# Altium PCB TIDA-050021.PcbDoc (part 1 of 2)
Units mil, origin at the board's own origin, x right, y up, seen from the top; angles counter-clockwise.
Board outline 3800 x 2400 mil, 4 copper layers (Top Layer, Signal Layer 1, Signal Layer 2, Bottom Layer), stack 51.2 mil thick; 78 components, 31 nets, 172 pads, 126 vias.
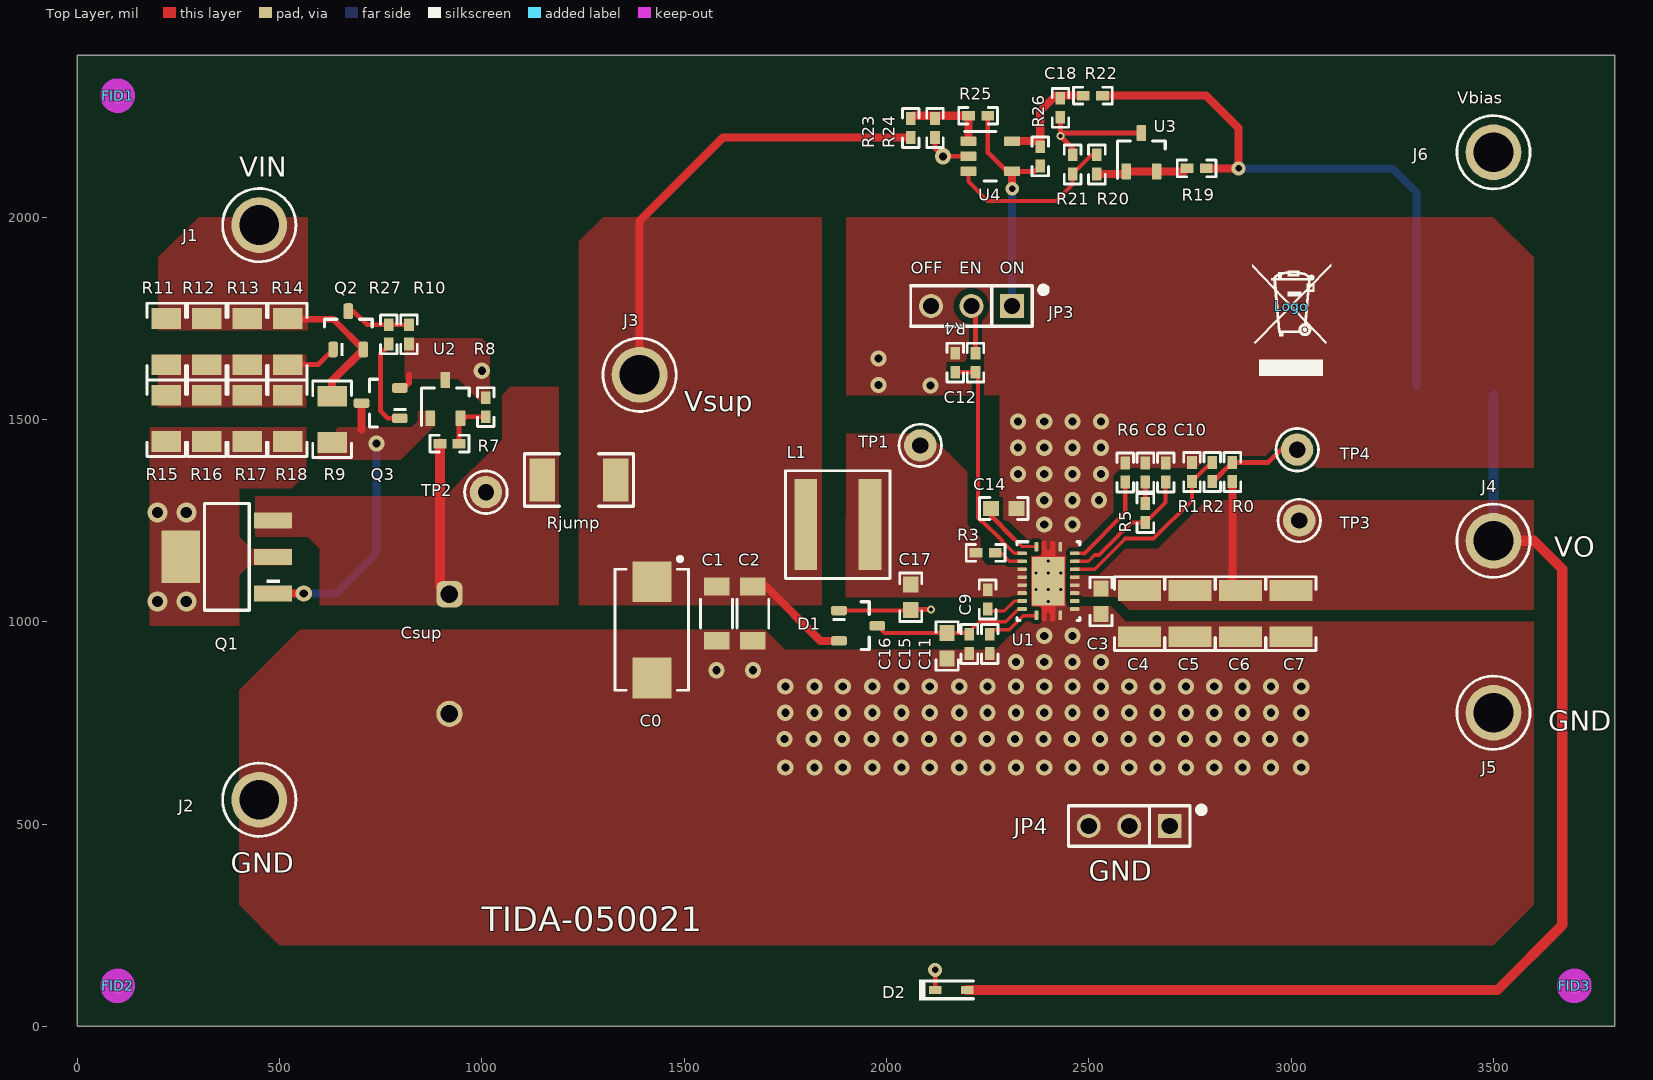
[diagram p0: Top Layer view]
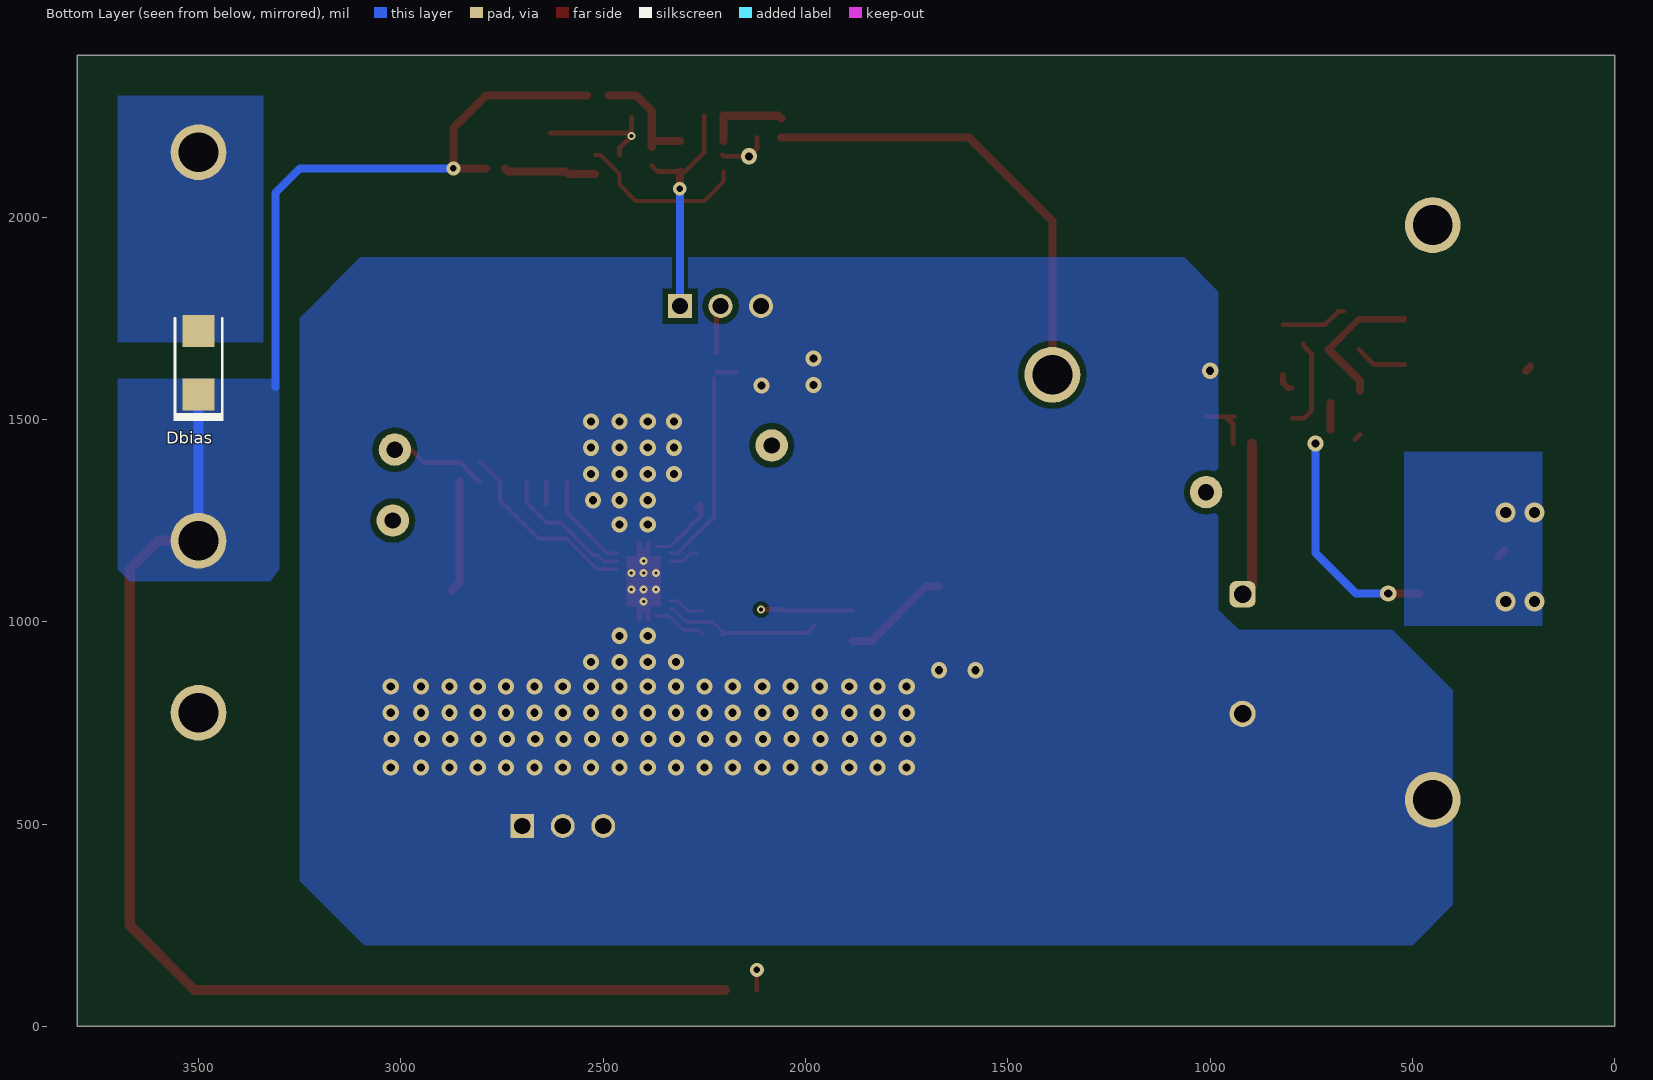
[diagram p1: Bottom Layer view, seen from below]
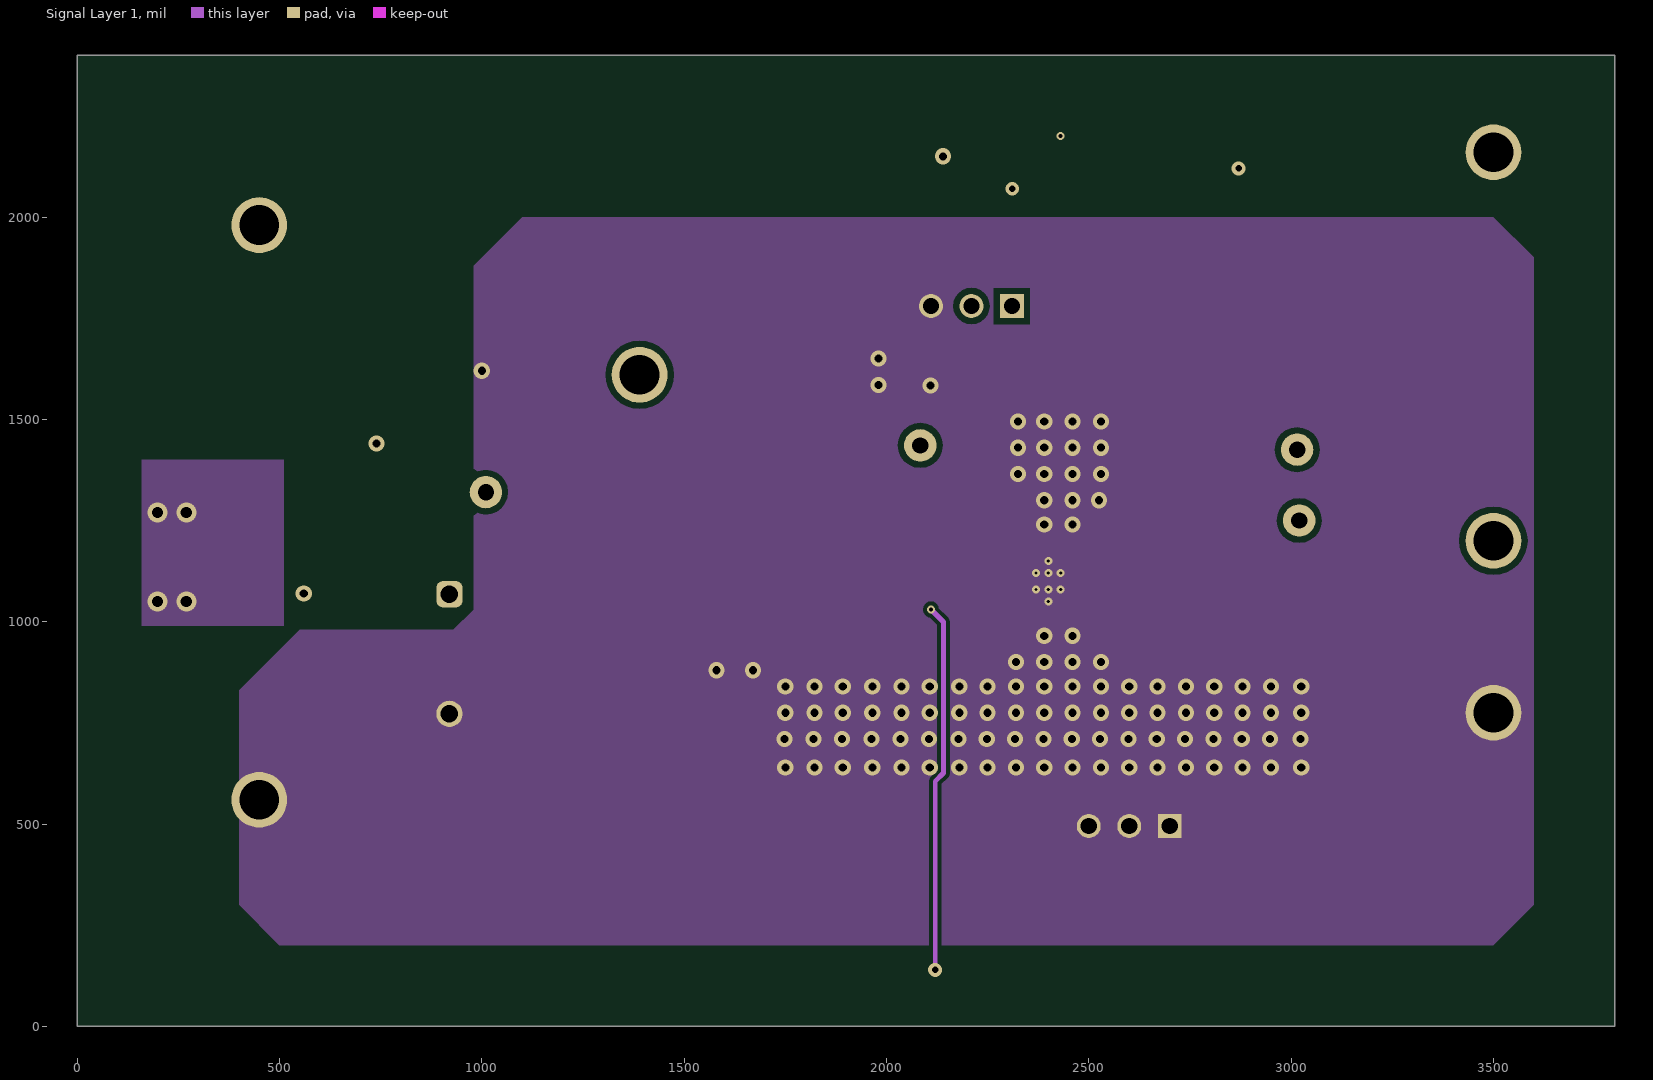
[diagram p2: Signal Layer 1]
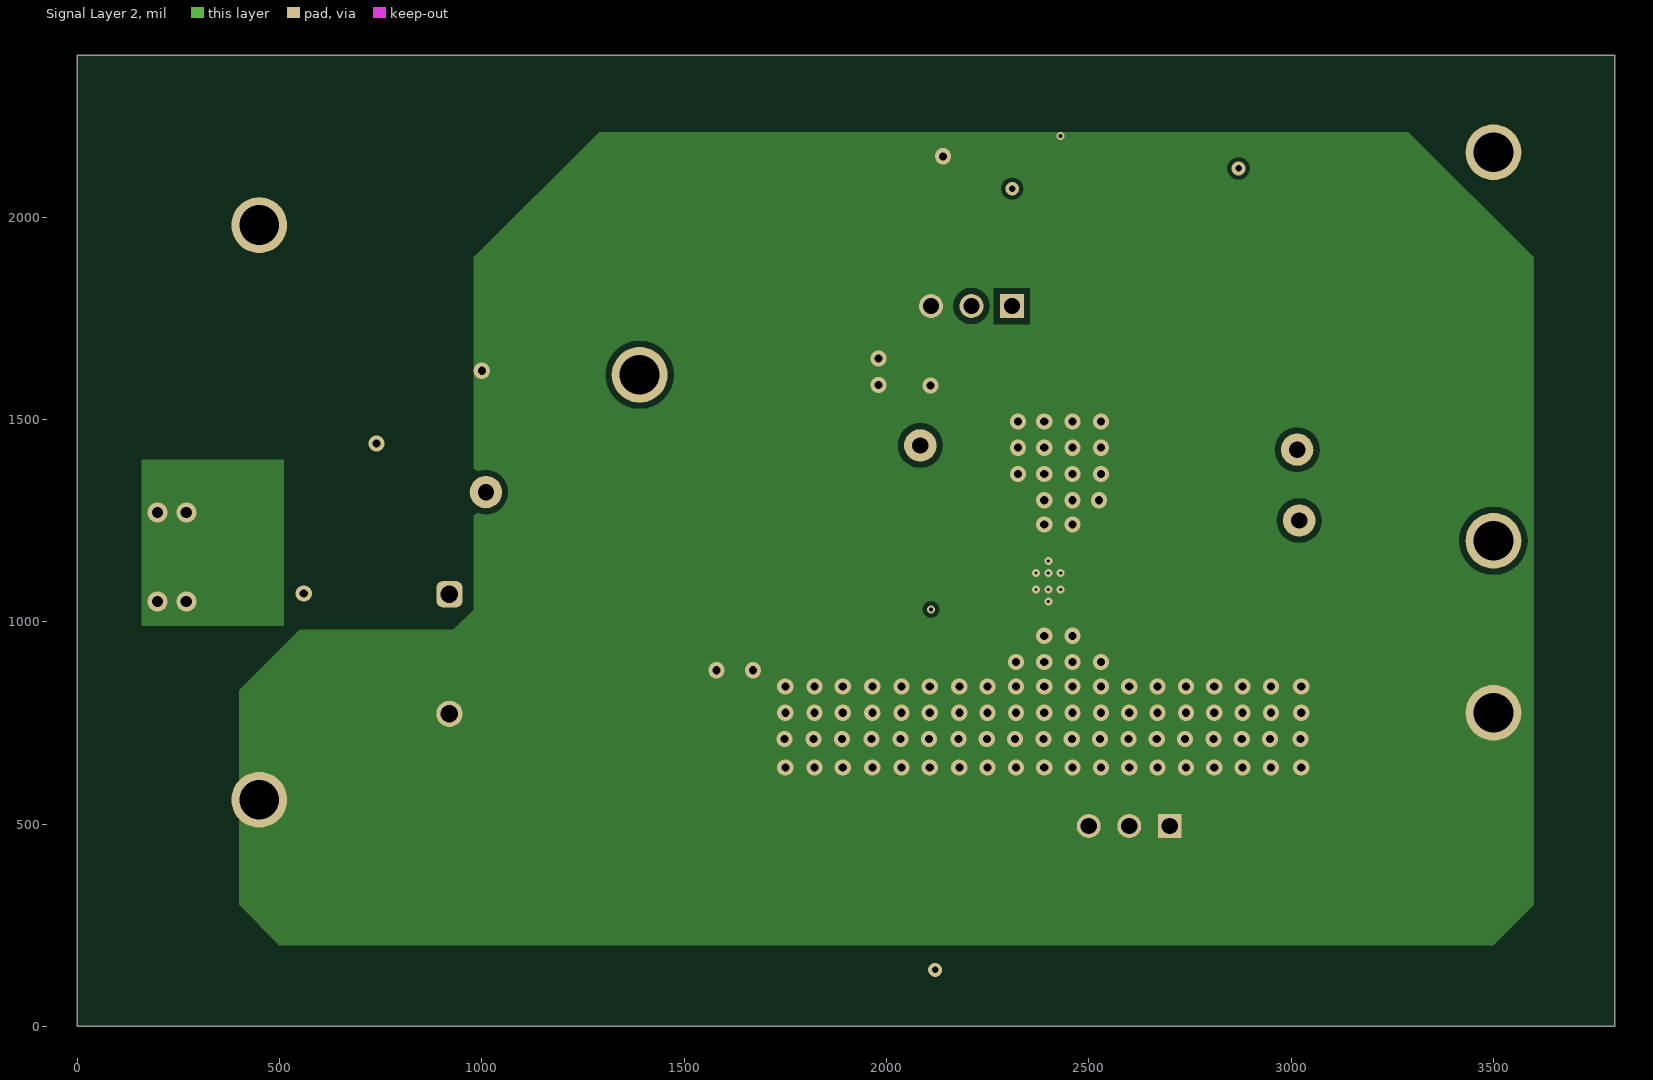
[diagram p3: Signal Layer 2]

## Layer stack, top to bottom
Top Solder: solder mask 0.4, Solder Resist, Dk 3.5
Top Layer: signal copper 2.8
Dielectric1: core 10, FR-4, Dk 4.8
Signal Layer 1: signal copper 2.8
Dielectric 3: dielectric 20, Dk 4.2
Signal Layer 2: signal copper 2.8
Dielectric 2: dielectric 10, Dk 4.8
Bottom Layer: signal copper 2.8
Bottom Solder: solder mask 0.4, Solder Resist, Dk 3.5

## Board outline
0,0 3800,0 3800,2400 0,2400

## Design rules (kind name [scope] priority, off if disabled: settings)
AcuteAngle [All] p1: minimum=4.50000000000000E+0001 checktracksonly=FALSE
AssemblyTestPointUsage [All] p1: valid=2
BoardOutlineClearance BoardOutlineClearance_MountingHoles [OnCopper and InComponentClass('Mounting Holes')] p1: gap=40 ignorepadtopadclearanceinfootprint=FALSE
BoardOutlineClearance BoardOutlineClearance_Poly [OnCopper and IsPoly] p2: gap=25 ignorepadtopadclearanceinfootprint=FALSE
BoardOutlineClearance [OnCopper and Not InComponentClass('Logo') and not InComponentClass('FiducialMark') and not InRegion(1000,500,4000,800) and not InPoly] p3: gap=75 ignorepadtopadclearanceinfootprint=FALSE
Clearance Clearance_Keepouts [((IsTrack Or IsArc) And Not InPoly) And IsFree and IsKeepOut vs ((IsTrack Or IsArc) And Not InPoly) And IsFree and IsKeepOut] p1: gap=0 ignorepadtopadclearanceinfootprint=FALSE
Clearance Clearance_Poly [InPolygon] p2: gap=10 ignorepadtopadclearanceinfootprint=FALSE except(0: Arc-Hole Track-Hole SMDPad-Hole THPad-Hole Via-Hole Fill-Hole Poly-Hole Region-Hole Text-Hole; 12: Arc-Via Track-Via SMDPad-Via; 15: Arc-THPad Track-THPad SMDPad-THPad THPad-THPad THPad-Via THPad-Fill THPad-Poly THPad-Region)
Clearance Clearance_FiducialMark [IsKeepOut and InComponentClass('FiducialMark') vs IsPad and InComponentClass('FiducialMark')] p3: gap=0 ignorepadtopadclearanceinfootprint=FALSE
Clearance [All] p4: gap=7.87 ignorepadtopadclearanceinfootprint=FALSE except(0: Arc-Hole Track-Hole SMDPad-Hole THPad-Hole Via-Hole Fill-Hole Poly-Hole Region-Hole Text-Hole)
ComponentClearance ComponentClearance_MountingHoles_FiducialMarks [InComponentClass('Mounting Holes') vs InComponentClass('FiducialMark')] p1: gap=50 collisioncheckmode=3 verticalgap=10 showdistances=FALSE
ComponentClearance ComponentClearance_Shunt [InComponentClass('Header') vs InComponentClass('Shunt')] p2: gap=0 collisioncheckmode=3 verticalgap=0 showdistances=FALSE
ComponentClearance ComponentClearance_Logo [InComponentClass('Logo')] p3: gap=50 collisioncheckmode=3 verticalgap=10 showdistances=FALSE
ComponentClearance ComponentClearance_ScrewToNut [(HasFootprint('NY PMS 440 0025 PH')) vs (HasFootprint('Keystone_1902C'))] p4: gap=5 collisioncheckmode=3 verticalgap=10 showdistances=FALSE
ComponentClearance ComponentClearance_MountingHoles [InComponentClass('Mounting Holes')] p5: gap=250 collisioncheckmode=3 verticalgap=100000 showdistances=FALSE
ComponentClearance ComponentClearance_SmallPassives [HasFootprint('0201*') or HasFootprint('0402*') or HasFootprint('0508') or HasFootprint('0603*') or HasFootprint('0612') or HasFootprint('0805*') or HasFootprint('0815*') or HasFootprint('0830*') or HasFootprint('1206*') or HasFootprint('1210*') or HasFootprint('1808*') or HasFootprint('1812*') or HasFootprint('1825*') or HasFootprint('2010*') or HasFootprint('2220*') or HasFootprint('2225*') or HasFootprint('2512*') or HasFootprint('2728*') or HasFootprint('3518*') vs HasFootprint('0201*') or HasFootprint('0402*') or HasFootprint('0508') or HasFootprint('0603*') or HasFootprint('0612') or HasFootprint('0805*') or HasFootprint('0815*') or HasFootprint('0830*') or HasFootprint('1206*') or HasFootprint('1210*') or HasFootprint('1808*') or HasFootprint('1812*') or HasFootprint('1825*') or HasFootprint('2010*') or HasFootprint('2220*') or HasFootprint('2225*') or HasFootprint('2512*') or HasFootprint('2728*') or HasFootprint('3518*')] p6: gap=14.96 collisioncheckmode=3 verticalgap=10 showdistances=FALSE
ComponentClearance ComponentClearance_THtoSMT [IsThruComponent vs IsSMTComponent] p7: gap=40 collisioncheckmode=3 verticalgap=30 showdistances=FALSE
ComponentClearance ComponentClearance_THtoTH [IsThruComponent vs IsThruComponent] p8: gap=30 collisioncheckmode=3 verticalgap=30 showdistances=FALSE
ComponentClearance [All] p9: gap=30 collisioncheckmode=3 verticalgap=10 showdistances=FALSE
DiffPairsRouting [All] p1: maxlimit=100 minlimit=10 mostfreqgap=10 toplayer_minwidth=15 toplayer_maxwidth=15 toplayer_prefwidth=15 midlayer1_minwidth=15 midlayer1_maxwidth=15 midlayer1_prefwidth=15 midlayer2_minwidth=15 midlayer2_maxwidth=15 midlayer2_prefwidth=15 bottomlayer_minwidth=15 bottomlayer_maxwidth=15 bottomlayer_prefwidth=15 maxuncoupledlength=1000
FabricationTestPointUsage TestPointUsage [All] p1: valid=2 allowmultiple=FALSE
FabricationTestpoint Testpoint [All] p1: side=3 testpointundercomponent=TRUE minsize=40 maxsize=100 preferedsize=60 minholesize=0 maxholesize=40 preferedholesize=32 testpointgrid=1 allowsidetop=TRUE allowsidebottom=TRUE usegrid=TRUE gridtolerance=0.01
FanoutControl Fanout_LCC [IsLCC] p1: bgadir=Out bgaviamode=Centered fanoutstyle=Auto fanoutdirection=Alternating viagrid=1 // Fanout_LCC (Default Rule)
FanoutControl Fanout_BGA [IsBGA] p2: bgadir=Out bgaviamode=Centered fanoutstyle=Auto fanoutdirection=Alternating viagrid=1 // Fanout_BGA (Default Rule)
FanoutControl Fanout_Default [All] p4: bgadir=Out bgaviamode=Centered fanoutstyle=Auto fanoutdirection=Alternating viagrid=1 // Fanout_Default (Default Rule)
FanoutControl Fanout_Small [(CompPinCount < 5)] p5: bgadir=Out bgaviamode=Centered fanoutstyle=Auto fanoutdirection=OutThenIn viagrid=1 // Fanout_Small (Default Rule)
HoleSize [All] p1: absolutevalues=TRUE maxlimit=251 minlimit=7.87 maxpercent=80.000 minpercent=20.000
MinimumAnnularRing MinimumAnnularRing_ThermalPadVias [IsVia and InAnyComponent] p1: minimumring=5.91
MinimumAnnularRing [All] p2: minimumring=8
MinimumSolderMaskSliver MinimumSolderMaskSliver_Logo [InComponentClass('Logo') vs InComponentClass('Logo')] p1: minsoldermaskwidth=0.7
MinimumSolderMaskSliver [All] p2: minsoldermaskwidth=3.94
PlaneConnect [All] p1: planeconnectstyle=Relief reliefexpansion=10 reliefentries=4 reliefconductorwidth=10 reliefairgap=10
PolygonConnect [All] p1: connectstyle=Direct reliefconductorwidth=10 reliefentries=4 polygonreliefangle="90 Angle" airgapwidth=10
RoutingVias ThermalPadVias [IsVia and InAnyComponent] p1: holewidth=7.87 width=19.68 viastyle="Through Hole" minholewidth=7.87 minwidth=19.68 maxholewidth=12.99 maxwidth=23.62
RoutingVias [All] p2: holewidth=16 width=34 viastyle="Through Hole" minholewidth=7.87 minwidth=26 maxholewidth=40 maxwidth=65
SilkToBoardRegionClearance [Not ((IsComment or IsDesignator) And (Hide <> 'False')) and not InRegion(1000,500,4000,800)] p1:
SilkToSilkClearance SilkToSilkClearance_Pb-FreeLogo [(HasFootprint('Pb-Free_Overlay_Medium') OR HasFootprint('Pb-Free_Overlay_Small')) vs (HasFootprint('Pb-Free_Overlay_Medium') OR HasFootprint('Pb-Free_Overlay_Small'))] p1: silktosilkclearance=0
SilkToSilkClearance [All] p2: silktosilkclearance=4
SilkToSolderMaskClearance SilkToComponentPadClearance [(IsPad or IsFill or IsRegion) and InAnycomponent] p1: minsilkscreentomaskgap=5 clearancetoexposedcopper=TRUE
SilkToSolderMaskClearance "Silk to Solder Mask Opening" [All] p2: minsilkscreentomaskgap=4 clearancetoexposedcopper=FALSE
SolderMaskExpansion [All] p1: expansion=1.97
Width [All] p1: maxlimit=100 minlimit=6 preferedwidth=10 checkconnectedcopper=TRUE
15 further rules are at their usual default settings.

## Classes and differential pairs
component class Header: JP3 JP4
component class TIDA-050021: C0 C1 C2 C3 C4 C5 C6 C7 C8 C9 C10 C11 C12 C14 C15 C16 C17 C18 Csup D1 D2 Dbias J1 J2 J3 J4 J5 J6 JP3 JP4 L1 Q1 Q2 Q3 R0 R1 R2 R3 R4 R5 R6 R7 R8 R9 R10 R11 R12 R13 R14 R15 R16 R17 R18 R19 R20 R21 R22 R23 R24 R25 R26 R27 Rjump TP1 TP2 TP3 TP4 U1 U2 U3 U4
component class AssemblyNote: ZZ2 ZZ3 ZZ4
component class FiducialMark: FID1 FID2 FID3
component class TIDA-050021_Hardware: FID1 FID2 FID3 Logo ZZ2 ZZ3 ZZ4

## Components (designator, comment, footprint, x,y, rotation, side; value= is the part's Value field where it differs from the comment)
C0 "T495X107K016ATE100" 7343-43 1420,980 r270 top value=100uF
C1 "GRM31CR61C226KE15L" 1206_180 1580,1020 r270 top value=22uF
C2 "GRM31CR61C226KE15L" 1206_180 1670,1020 r270 top value=22uF
C3 "GRM188R71E105KA12D" 0603 2530,1050 r270 top value=1uF
C4 "GRM32ER71E226KE15L" 1210_270 2625,1020 r270 top value=22uF
C5 "GRM32ER71E226KE15L" 1210_270 2750,1020 r270 top value=22uF
C6 "GRM32ER71E226KE15L" 1210_270 2875,1020 r270 top value=22uF
C7 "GRM32ER71E226KE15L" 1210_270 3000,1020 r270 top value=22uF
C8 "CGA2B3X7R1H103K050BB" 0402 2640,1368.62 r90 top value=0.01uF
C9 "GRM155R61C104KA88D" 0402 2250,1055 r270 top value=0.1uF
C10 "GRM1555C1H470FA01D" 0402 2690,1368.62 r90 top value=47pF
C11 "GRM155R71C473KA01D" 0402 2255,945 r90 top value=0.047uF
C12 "GRM155R61H472KA01D" 0402 2170,1640 r90 top value=4700pF
C14 "0603ZD475KAT2A" 0603 2290,1280 r180 top value=4.7uF
C15 "GRM155R61C104KA88D" 0402 2205,945 r270 top value=0.1uF
C16 "GRM188R71E105KA12D" 0603 2150,940 r270 top value=1uF
C17 "GRM188R61E104KA01D" 0603 2060,1060 r270 top value=0.1uF
C18 "GRM155R61A104KA01D" 0402 2430,2270 r270 top value=0.1uF
Csup "HV1625-2R7256-R" HV_1600x2840 920,920 r270 top value=25000000uF
D1 "BAT54C-7-F" SOT-23 1930,990 r0 top value=30V
D2 "1N4148WT" Fairchild_SOD-523F 2160,90 r0 top value=75V
Dbias "MBRA210LT3G" SMA 3500,1640 r90 bottom value=10V
FID1 "Fiducial" Fiducial10-20 100,2300 r0 top
FID2 "Fiducial" Fiducial10-20 100,100 r0 top
FID3 "Fiducial" Fiducial10-20 3700,100 r0 top
J1 "Suggest using a net name here" Keystone1502-2 450,1980 r0 top value=Double
J2 "Suggest using a net name here" Keystone1502-2 450,560 r0 top value=Double
J3 "Suggest using a net name here" Keystone1502-2 1390,1610 r0 top value=Double
J4 "Suggest using a net name here" Keystone1502-2 3500,1200 r0 top value=Double
J5 "Suggest using a net name here" Keystone1502-2 3500,775 r0 top value=Double
J6 "Suggest using a net name here" Keystone1502-2 3500,2160 r0 top value=Double
JP3 "PEC03SAAN" CONN_PEC03SAAN 2210,1780 r180 top
JP4 "PEC03SAAN" CONN_PEC03SAAN 2600,495 r180 top
L1 "XAL6030-102MEB" XAL6030 1880,1240 r0 top value=1uH
Logo "WEEE logo" WEEE_Minimum 3000,1780 r0 top
Q1 "NSS40301MZ4T1G" SOT-223 370,1160 r180 top value="40 V"
Q2 "BC857C-7-F" SOT-23 670,1720 r90 top value="45 V"
Q3 "BC847CLT1G" SOT-23 750,1540 r180 top value="45 V"
R0 "CRCW040249R9FKED" 0402 2855,1370 r270 top value=49.9
R1 "CRCW040256K2FKED" 0402 2755,1370 r270 top value=56.2k
R2 "CRCW0402121KFKED" 0402 2805,1370 r270 top value=121k
R3 "CRCW0402255KFKED" 0402 2245,1170 r180 top value=255k
R4 "MCR01MZPF10R0" 0402 2220,1640 r270 top value=10.0
R5 "CRCW04024K99FKED" 0402 2640,1268.62 r270 top value=4.99k
R6 "CRCW040290K9FKED" 0402 2590,1368.62 r270 top value=90.9k
R7 "CRCW04026K04FKED" 0402 920,1440 r180 top value=6.04k
R8 "CRCW0402100KFKED" 0402 1010,1530 r270 top value=100k
R9 "CRCW120620R0FKEAHP" 1206 630,1500 r270 top value=20.0
R10 "ERJ-2RKF3300X" 0402 820,1710 r90 top value=330
R11 "CRCW12063R60JNEA" 1206 220,1692.36 r270 top value=3.6
R12 "CRCW12063R60JNEA" 1206 320,1692.36 r270 top value=3.6
R13 "CRCW12063R60JNEA" 1206 420,1692.36 r270 top value=3.6
R14 "CRCW12063R60JNEA" 1206 520,1692.36 r270 top value=3.6
R15 "CRCW12063R60JNEA" 1206 220,1502.36 r270 top value=3.6
R16 "CRCW12063R60JNEA" 1206 320,1502.36 r270 top value=3.6
R17 "CRCW12063R60JNEA" 1206 420,1502.36 r270 top value=3.6
R18 "CRCW12063R60JNEA" 1206 520,1502.36 r270 top value=3.6
R19 "CRCW04021K00FKED" 0402 2766.56,2120.2 r180 top value=1.00k
R20 "ERJ-2RKF1503X" 0402 2520,2130 r90 top value=150k
R21 "CRCW0402100KFKED" 0402 2460,2130 r270 top value=100k
R22 "MCR01MZPF10R0" 0402 2510,2300 r0 top value=10.0
R23 "CRCW0402100KFKED" 0402 2060,2220 r270 top value=100k
R24 "CRCW0402113KFKED" 0402 2120,2220 r90 top value=113k
R25 "CRCW0402316KFKED" 0402 2226.56,2250.2 r0 top value=316k
R26 "CRCW040210K0FKED" 0402 2380,2150 r90 top value=10.0k
R27 "CRCW0402100RFKED" 0402 770,1710 r270 top value=100
Rjump "CRCW20100000Z0EF" 2010 1240,1350 r180 top value=0
TP1 "5003" Keystone5003 2083.58,1435.64 r90 top value=Orange
TP2 "5003" Keystone5003 1010,1320 r90 top value=Orange
TP3 "5003" Keystone5003 3020,1250 r180 top value=Orange
TP4 "5003" Keystone5003 3015,1425 r0 top value=Orange
U1 "TPS61088QRHLTQ1" RHL0020A 2400,1100 r0 top
U2 "ATL431AIDBZR" DBZ0003A_N 910,1550 r90 top
U3 "ATL431AIDBZR" DBZ0003A_N 2630,2160 r90 top
U4 "LMV331IDBV" DBV0005A_N 2256.56,2150.2 r0 top
ZZ2 "These assemblies are ESD sensitive, ESD precautions shall be observed." AssemblyNote 185,3829.11 r0 top
ZZ3 "These assemblies must be clean and free from flux and all contaminants. Use of no clean flux is not acceptable." AssemblyNote 185,3740.56 r0 top
ZZ4 "These assemblies must comply with workmanship standards IPC-A-610 Class 2, unless otherwise specified." AssemblyNote 185,3652 r0 top

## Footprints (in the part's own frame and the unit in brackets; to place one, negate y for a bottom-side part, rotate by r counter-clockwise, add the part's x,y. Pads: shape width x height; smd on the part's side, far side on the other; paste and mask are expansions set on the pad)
0402 [mm] "0402 from SM-752 data"
  rect 0.8x0.6 smd: 1(-0.6,0) 2(0.6,0)
  silkscreen extent -1.22,-0.52 1.22,0.52, body extent -0.55,-0.3 0.55,0.3, height 0.6
0603 [mm] "0603 from SM-752 data"
  rect 1x0.95 smd: 1(-0.8,0) 2(0.8,0)
  silkscreen extent -1.52,-0.69 1.52,0.69, body extent -0.87,-0.47 0.87,0.47, height 1
1206 [mm] "1206 from SM-752 data"
  rect 1.3x1.85 smd: 1(-1.45,0) 2(1.45,0)
  silkscreen extent -2.4,-1.21 2.4,1.21, body extent -1.7,-0.9 1.7,0.9, height 1.35
1206_180 [mm] "1206_180"
  rect 1.1x1.6 smd: 1(-1.7,0) 2(1.7,0)
  silkscreen extent -0.9,-1 0.9,1, body extent -1.75,-0.95 1.75,0.95, height 1.8
1210_270 [mm] "1210"
  rect 1.3x2.7 smd: 1(-1.45,0) 2(1.45,0)
  silkscreen extent -2.32,-1.57 2.32,1.57, body extent -1.7,-1.35 1.7,1.35, height 2.7
2010 [mm] "Chip Capacitor, Body 5.08x2.54mm, IPC Medium Density"
  rect 1.6x2.7 smd: 1(-2.3,0) 2(2.3,0)
  silkscreen extent -3.42,-1.65 3.42,1.65, body extent -2.73,-1.45 2.73,1.45, height 1.66
7343-43 [mm] "Medium density IPC based on Kemet T495 series"
  rect 2.55x2.45 smd: 1(-3.025,0) 2(3.025,0)
  silkscreen extent -4.56,-2.3 3.8,2.3, body extent -3.8,-2.3 3.8,2.3, height 4.3
AssemblyNote [mil] "Assembly Note"
CONN_PEC03SAAN [mm] "SULLINS"
  rect 1.5x1.5 hole 1.016: 1(-2.54,0)
  round 1.5 hole 1.016: 2(0,0) 3(2.54,0)
  silkscreen extent -4.72,-1.27 3.81,1.27, body extent -3.84,-1.3 3.84,1.3, height 8.38
DBV0005A_N [mm] "SOT23, 5-Leads, Body 2.9x1.6mm, Pitch 0.95mm, Lead Span 2.8mm, IPC Medium Density"
  rrect17% 1x0.6 smd: 1(-1.375,0.95) 2(-1.375,0) 3(-1.375,-0.95) 4(1.375,-0.95) 5(1.375,0.95)
  silkscreen extent -1.63,-1.55 0.38,1.55, body extent -1.42,-1.46 1.42,1.46, height 1.09
DBZ0003A_N [mm] "SOT23, 3-Leads, Body 2.9x1.3mm, Pitch 0.95mm, Lead Span 2.4mm, IPC Medium Density"
  rrect17% 1x0.6 smd: 1(-1.2,0.95) 2(-1.2,-0.95) 3(1.2,0)
  silkscreen extent -1.65,-1.5 0.7,1.5, body extent -1.26,-1.46 1.26,1.46, height 0.98
Fairchild_SOD-523F [mm] "SMD, 2-Leads, Body 1.2x0.8mm"
  rect 0.8x0.5 smd: 1(-1,0) 2(1,0)
  silkscreen extent -2.03,-0.65 1.4,0.65, body extent -0.65,-0.45 0.65,0.45, height 0.7
Fiducial10-20 [mm]
  round 1 smd mask+0.5: 1(0,0)
  Top Layer keep-out circle w1.178: c0,0 r0.5
HV_1600x2840 [mm] "TH, 2-Leads, Dia 16mm, Pin Spacing 7.5mm"
  rrect50% 1.65x1.65 hole 1.1: 1(-3.75,0)
  round 1.65 hole 1.1: 2(3.75,0)
  body extent -8.25,-8.25 8.26,8.25, height 28.4
Keystone1502-2 [mm] "Double Turret"
  round 3.5 hole 2.5: 1(0,0)
  silkscreen extent -2.3,-2.3 2.3,2.3, body extent -1.6,-1.6 1.59,1.6, height 5.62
Keystone5003 [mil] "For Keystone 500x miniature loop terminals"
  round 80 hole 40: 1(0,0)
  silkscreen extent -52,-52 52,52, body extent -49,-49 49,49, height 182
RHL0020A [mm] "QFN, 20-Leads, Body 4.5x3.5mm, Pitch 0.5mm, Thermal Pad 3.05x2.05mm, TI Recommended"
  rrect42% 0.24x0.6 smd: 1(-0.75,2.15) 10(-0.75,-2.15) 11(0.75,-2.15) 20(0.75,2.15)
  rrect42% 0.6x0.24 smd: 2(-1.65,1.75) 3(-1.65,1.25) 4(-1.65,0.75) 5(-1.65,0.25) 6(-1.65,-0.25) 7(-1.65,-0.75) 8(-1.65,-1.25) 9(-1.65,-1.75) 12(1.65,-1.75) 13(1.65,-1.25) 14(1.65,-0.75) 15(1.65,-0.25) 16(1.65,0.25) 17(1.65,0.75) 18(1.65,1.25) 19(1.65,1.75)
  rrect12% 0.92x0.85 on Top Paste: 21(-0.56,-1.05) 21(-0.56,0) 21(-0.56,1.05) 21(0.56,-1.05) 21(0.56,0) 21(0.56,1.05)
  rrect5% 2.05x3.05 smd paste-2 mask+0: 21(0,0)
  Top Layer region: -0.975,-1.575 -0.425,-1.575 -0.425,-2.4 -0.417,-2.438 -0.396,-2.471 -0.363,-2.492 -0.325,-2.5 -0.325,-2.5 -0.225,-2.5 -0.187,-2.492 -0.154,-2.471 -0.133,-2.438 -0.125,-2.4 -0.125,-2.4 -0.125,-1.975 0.125,-1.975 0.125,-2.4 0.133,-2.438 0.154,-2.471 0.187,-2.492 0.225,-2.5 0.225,-2.5 0.325,-2.5 0.363,-2.492 0.396,-2.471 0.417,-2.438 0.425,-2.4 0.425,-2.4 0.425,-1.575 0.975,-1.575 1.013,-1.567 1.046,-1.546 1.067,-1.513 1.075,-1.475 1.075,-1.475 1.075,1.475 1.067,1.513 1.046,1.546 1.013,1.567 0.975,1.575 0.975,1.575 0.425,1.575 0.425,2.4 0.417,2.438 0.396,2.471 0.363,2.492 0.325,2.5 0.325,2.5 0.225,2.5 0.187,2.492 0.154,2.471 0.133,2.438 0.125,2.4 0.125,2.4 0.125,1.975 -0.125,1.975 -0.125,2.4 -0.133,2.438 -0.154,2.471 -0.187,2.492 -0.225,2.5 -0.225,2.5 -0.325,2.5 -0.363,2.492 -0.396,2.471 -0.417,2.438 -0.425,2.4 -0.425,2.4 -0.425,1.575 -0.975,1.575 -1.013,1.567 -1.046,1.546 -1.067,1.513 -1.075,1.475 -1.075,1.475 -1.075,-1.475 -1.067,-1.513 -1.046,-1.546 -1.013,-1.567 -0.975,-1.575
  silkscreen extent -1.98,-2.47 1.98,2.47, body extent -1.75,-2.25 1.75,2.25, height 1.01
SMA [mm] "Molded Diode, 2-Leads, Body 4.3x2.6mm, IPC Medium Density, based on OnSemi component dimensions and land pattern"
  rect 2x2 smd: 1(-2,0) 2(2,0)
  silkscreen extent -3.66,-1.57 2.79,1.57, body extent -2.6,-1.3 2.6,1.3, height 2.42
SOT-23 [mm] "SOT23, 3-Leads, Body 2.9x1.3mm, Pitch 0.95mm, Lead Span 2.5mm, IPC Medium Density"
  rrect50% 1x0.6 smd: 1(-1.2,0.95) 2(-1.2,-0.95) 3(1.2,0)
  silkscreen extent -1.63,-1.5 0.7,1.5, body extent -1.16,-1.45 1.21,1.45, height 1
SOT-223 [mm] "SOT223/SC73, 4-Leads, Body 6.5x3.5mm, Pitch 2.3mm, Lead Span 7mm, IPC Medium Density"
  rrect10% 2.4x1 smd: 1(-2.9,2.3) 2(-2.9,0) 3(-2.9,-2.3)
  rrect4% 2.4x3.3 smd: 4(2.9,0)
  silkscreen extent -3.33,-3.35 1.4,3.35, body extent -3.5,-3.25 3.5,3.25, height 1.62
WEEE_Minimum [mil] "WEEElie bin"
  silkscreen extent -95,-172 99,104
XAL6030 [mil] "Coilcraft recommended land pattern Document 887-4 Revised 11/20/12"
  rect 56x224 smd: 1(-79.5,0) 2(79.5,0)
  silkscreen extent -129,-133 129,133, body extent -129,-133 129,133, height 122

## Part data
C0: "CAP, TA, 100 µF, 16 V, +/- 10%, 0.1 ohm, SMD", Cap_Case=X, Manufacturer=Kemet, Supplier Part Number 1=399-3895-1-ND, Tolerance_%=10, Value1="0.1 ohm", Value2=16V, ValueDisplayed=100µF
C1 C2: "CAP, CERM, 22 µF, 16 V,+/- 10%, X5R, 1206", Cap_Case=1206, Manufacturer=MuRata, Supplier Part Number 1=GRM31CR61C226KE15L-ND, TempCo=X5R, Tolerance_%=10, Value2=16V, ValueDisplayed=22µF
C3 C16: "CAP, CERM, 1 µF, 25 V, +/- 10%, X7R, 0603", Cap_Case=0603, Manufacturer=MuRata, Supplier Part Number 1=490-5307-1-ND, TempCo=X7R, Tolerance_%=10, Value1=Unknown, Value2=25V, ValueDisplayed=1µF
C4 C5 C6 C7: "CAP, CERM, 22 µF, 25 V,+/- 10%, X7R, 1210", Cap_Case=1210, Manufacturer=MuRata, Supplier Part Number 1=490-5313-1-ND, TempCo=X7R, Tolerance_%=10, Value1="0.002334 ohm", Value2=25V, ValueDisplayed=22µF
C8: "CAP, CERM, 0.01 µF, 50 V,+/- 10%, X7R, AEC-Q200 Grade 1, 0402", Cap_Case=0402, Manufacturer=TDK, Supplier Part Number 1=445-6893-1-ND, TempCo=X7R, Tolerance_%=10, Value1="0.333065 ohm", Value2=50V, ValueDisplayed=0.01µF
C9 C15: "CAP, CERM, 0.1uF, 16V, +/-10%, X5R, 0402", Cap_Case=0402, Manufacturer=MuRata, Supplier Part Number 1=490-5415-1-ND, TempCo=X5R, Tolerance_%=10, Value1=Unknown, Value2=16V, ValueDisplayed=0.1uF
C10: "CAP, CERM, 47 pF, 50 V, +/- 1%, C0G, 0402", Cap_Case=0402, Manufacturer=MuRata, Supplier Part Number 1=490-6241-1-ND, TempCo=C0G, Tolerance_%=1, Value1=Unknown, Value2=50V, ValueDisplayed=47pF
C11: "CAP, CERM, 0.047 µF, 16 V, +/- 10%, X7R, 0402", Cap_Case=0402, Manufacturer=MuRata, Supplier Part Number 1=GRM155R71C473KA01D-ND, TempCo=X7R, Tolerance_%=10, Value1=Unknown, Value2=16V, ValueDisplayed=0.047µF
C12: "CAP, CERM, 4700 pF, 50 V, +/- 10%, X5R, 0402", Cap_Case=0402, Manufacturer=MuRata, Supplier Part Number 1=GRM155R61H472KA01D-ND, TempCo=X5R, Tolerance_%=10, Value1=Unknown, Value2=50V, ValueDisplayed=4700pF
C14: "CAP, CERM, 4.7uF, 10V, +/-10%, X5R, 0603", Cap_Case=0603, Manufacturer=AVX, Supplier Part Number 1=478-7943-1-ND, TempCo=X5R, Tolerance_%=10, Value1=Unknown, Value2=10V, ValueDisplayed=4.7uF
C17: "CAP, CERM, 0.1 µF, 25 V,+/- 10%, X5R, 0603", Cap_Case=0603, Manufacturer=MuRata, Supplier Part Number 1=GRM188R61E104KA01D-ND, TempCo=X5R, Tolerance_%=10, Value2=25V, ValueDisplayed=0.1µF
C18: "CAP, CERM, 0.1 µF, 10 V,+/- 10%, X5R, 0402", Cap_Case=0402, Manufacturer=MuRata, Supplier Part Number 1=490-1318-1-ND, TempCo=X5R, Tolerance_%=10, Value2=10V, ValueDisplayed=0.1µF
Csup: library part CMP-0084049-1, "CAP, Electric Double Layer, 25000000 µF, 2.7 V,+30/-10%, 0.027 ohm, TH", Cap_Case=16x28.4mm, Manufacturer=Eaton, Tolerance_%=30%, Value1="0.027 ohm", Value2=2.7V, ValueDisplayed=25000000µF
D1: "Diode, Schottky, 30 V, 0.2 A, SOT-23", Manufacturer="Diodes Inc.", Supplier Part Number 1=BAT54C-FDICT-ND, Value1=0.2A, Value2=0.65V
D2: "Diode, Switching, 75 V, 0.3 A, SMD, 2-Leads, Body 1.2x0.8mm", Manufacturer="Fairchild Semiconductor", Supplier Part Number 1=1N4148WTCT-ND, Value1=0.3A, Value2=V
Dbias: "Diode, Schottky, 10 V, 2 A, SMA", Manufacturer="ON Semiconductor", Supplier Part Number 1=MBRA210LT3GOSCT-ND, Value1=2A, Value2=0.35V
FID1 FID2 FID3: library part CMP-0077181-1, "Fiducial mark.  There is nothing to buy or mount.", Manufacturer=N/A
J1 J2 J3 J4 J5 J6: library part 1502-2, "Terminal, Turret, TH, Double", Manufacturer=Keystone, Supplier Part Number 1=1502-2K-ND
JP3 JP4: "Header, 100mil, 3x1, Tin, TH", Color=Black, Current_A=3, Manufacturer="Sullins Connector Solutions", Supplier Part Number 1=S1012E-03-ND, Voltage_V=1800
L1: "Inductor, Shielded, Composite, 1 µH, 21.5 A, 0.01 ohm, SMD", Manufacturer=Coilcraft, Value1="0.01 ohm", Value2=21.5A, ValueDisplayed=1µH
Logo: library part CMP-0074769-1
Q1: library part "NSS40301MZ4T1G, ON Semiconductor", "Transistor, NPN, 40 V, 3 A, SOT-223", Manufacturer="ON Semiconductor", Supplier Part Number 1=NSS40301MZ4T1GOSCT-ND, Value1="3 A", Value2=500
Q2: library part "BC857C-7-F, Diodes Inc.", "Transistor, PNP, 45 V, 0.1 A, SOT-23", Manufacturer="Diodes Inc.", Supplier Part Number 1=BC857C-FDICT-ND, Value1="0.1 A", Value2=600
Q3: library part "BC847CLT1G, ON Semiconductor", "Transistor, NPN, 45 V, 0.1 A, SOT-23", Manufacturer="ON Semiconductor", Supplier Part Number 1=BC847CLT1GOSCT-ND, Value1="0.1 A", Value2=800
R0: "RES, 49.9 ohm, 1%, 0.063W, 0402", Manufacturer=Vishay-Dale, Power_W=0.063, Supplier Part Number 1=541-49.9LCT-ND, TempCo="100 ppm/C", Tolerance_%=1, Value1=1%, Value2=0.063W, Value_Code=49R9
R1: "RES, 56.2 k, 1%, 0.063 W, 0402", Manufacturer=Vishay-Dale, Power_W=0.063, Supplier Part Number 1=541-56.2KLCT-ND, TempCo="100 ppm/C", Tolerance_%=1, Value1=1%, Value2=0.063W, Value_Code=56k2, ValueDisplayed=56.2k
R2: "RES, 121 k, 1%, 0.063 W, 0402", Manufacturer=Vishay-Dale, Power_W=0.063, Supplier Part Number 1=541-121KLCT-ND, TempCo="100 ppm/C", Tolerance_%=1, Value1=1%, Value2=0.063W, Value_Code=121k
R3: "RES, 255 k, 1%, 0.063 W, 0402", Manufacturer=Vishay-Dale, Power_W=0.063, Supplier Part Number 1=541-255KLCT-ND, TempCo="100 ppm/C", Tolerance_%=1, Value1=1%, Value2=0.063W, Value_Code=255k
R4 R22: "RES, 10.0, 1%, 0.063 W, 0402", Manufacturer=Rohm, Power_W=0.063, Supplier Part Number 1=RHM10.0LCT-ND, TempCo="100 ppm/C", Tolerance_%=1, Value1=1%, Value2=0.063W, Value_Code=10R0, ValueDisplayed=10.0
R5: "RES, 4.99 k, 1%, 0.063 W, 0402", Manufacturer=Vishay-Dale, Power_W=0.063, Supplier Part Number 1=541-4.99KLCT-ND, TempCo="100 ppm/C", Tolerance_%=1, Value1=1%, Value2=0.063W, Value_Code=4k99, ValueDisplayed=4.99k
R6: "RES, 90.9 k, 1%, 0.063 W, 0402", Manufacturer=Vishay-Dale, Power_W=0.063, Supplier Part Number 1=541-90.9KLCT-ND, TempCo="100 ppm/C", Tolerance_%=1, Value1=1%, Value2=0.063W, Value_Code=90k9, ValueDisplayed=90.9k
R7: "RES, 6.04 k, 1%, 0.063 W, 0402", Manufacturer=Vishay-Dale, Power_W=0.063, Supplier Part Number 1=541-6.04KLCT-ND, TempCo="100 ppm/C", Tolerance_%=1, Value1=1%, Value2=0.063W, Value_Code=6k04, ValueDisplayed=6.04k
R8 R21 R23: "RES, 100 k, 1%, 0.063 W, 0402", Manufacturer=Vishay-Dale, Power_W=0.063, Supplier Part Number 1=541-100KLCT-ND, TempCo="100 ppm/C", Tolerance_%=1, Value1=1%, Value2=0.063W, Value_Code=100k
R9: "RES, 20.0, 1%, 0.5 W, AEC-Q200 Grade 0, 1206", Manufacturer=Vishay-Dale, Power_W=0.5, Supplier Part Number 1=541-20.0UCT-ND, TempCo="100 ppm/C", Tolerance_%=1, Value1=1%, Value2=0.5W, Value_Code=20R0, ValueDisplayed=20.0
R10: "RES, 330, 1%, 0.1 W, AEC-Q200 Grade 0, 0402", Manufacturer=Panasonic, Power_W=0.1, Supplier Part Number 1=P330LCT-ND, TempCo="100 ppm/C", Tolerance_%=1, Value1=1%, Value2=0.1W, Value_Code=330R, ValueDisplayed=330
R11 R12 R13 R14 R15 R16 R17 R18: "RES, 3.6, 5%, 0.25 W, 1206", Manufacturer=Vishay-Dale, Power_W=0.25, Supplier Part Number 1=541-3.6ECT-ND, TempCo="200 ppm/C", Tolerance_%=5, Value1=5%, Value2=0.25W, Value_Code=3R60, ValueDisplayed=3.6
R19: "RES, 1.00 k, 1%, 0.063 W, 0402", Manufacturer=Vishay-Dale, Power_W=0.063, Supplier Part Number 1=541-1.00KLCT-ND, TempCo="100 ppm/C", Tolerance_%=1, Value1=1%, Value2=0.063W, Value_Code=1k00, ValueDisplayed=1.00k
R20: "RES, 150 k, 1%, 0.1 W, AEC-Q200 Grade 0, 0402", Manufacturer=Panasonic, Power_W=0.1, Supplier Part Number 1=P150KLCT-ND, TempCo="100 ppm/C", Tolerance_%=1, Value1=1%, Value2=0.1W, Value_Code=150k
R24: "RES, 113 k, 1%, 0.063 W, 0402", Manufacturer=Vishay-Dale, Power_W=0.063, Supplier Part Number 1=541-113KLCT-ND, TempCo="100 ppm/C", Tolerance_%=1, Value1=1%, Value2=0.063W, Value_Code=113k
R25: "RES, 316 k, 1%, 0.063 W, 0402", Manufacturer=Vishay-Dale, Power_W=0.063, Supplier Part Number 1=541-316KLCT-ND, TempCo="100 ppm/C", Tolerance_%=1, Value1=1%, Value2=0.063W, Value_Code=316k
R26: "RES, 10.0 k, 1%, 0.063 W, 0402", Manufacturer=Vishay-Dale, Power_W=0.063, Supplier Part Number 1=541-10.0KLCT-ND, TempCo="100 ppm/C", Tolerance_%=1, Value1=1%, Value2=0.063W, Value_Code=10k0, ValueDisplayed=10.0k
R27: "RES, 100, 1%, 0.063 W, 0402", Manufacturer=Vishay-Dale, Power_W=0.063, Supplier Part Number 1=541-100LCT-ND, TempCo="100 ppm/C", Tolerance_%=1, Value1=1%, Value2=0.063W, Value_Code=100R, ValueDisplayed=100
Rjump: "RES, 0, 5%, 0.75 W, AEC-Q200 Grade 0, 2010", Manufacturer=Vishay-Dale, Power_W=0.75, Supplier Part Number 1=541-0.0WCT-ND, TempCo=ppm/C, Tolerance_%=5, Value1=5%, Value2=0.75W, Value_Code=0000, ValueDisplayed=0
TP1 TP2 TP3 TP4: "Test Point, Miniature, Orange, TH", Manufacturer=Keystone, Supplier Part Number 1=36-5003-ND
U1: library part CMP-0082346-1, "10-A Fully-Integrated Synchronous Boost Converter, RHL0020A (VQFN-20)", Alternate Manufacturer="Texas Instruments", Alternate PartNumber=TPS61088QRHLRQ1, Operating Temperature Range="-40 to 125 C", Rating=Automotive
U2 U3: "2.5V Low Iq Adjustable Precision Shunt Regulator, DBZ0003A (SOT-23-3)", Alternate Manufacturer="Texas Instruments"
U4: "Single General Purpose Low-Voltage Comparator, DBV0005A", Alternate Manufacturer="Texas Instruments"
ZZ2: library part CMP-0077236-1
ZZ3: library part CMP-0077237-1
ZZ4: library part CMP-0077238-1

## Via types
v1: diameter 40, hole 20, Top Layer to Bottom Layer, 108 vias
v2: diameter 19.68, hole 7.87, Top Layer to Bottom Layer, 8 vias
v3: diameter 34, hole 16, Top Layer to Bottom Layer, 4 vias
v4: diameter 50, hole 28, Top Layer to Bottom Layer, 4 vias
v5: diameter 20, hole 10, Top Layer to Bottom Layer, 2 vias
